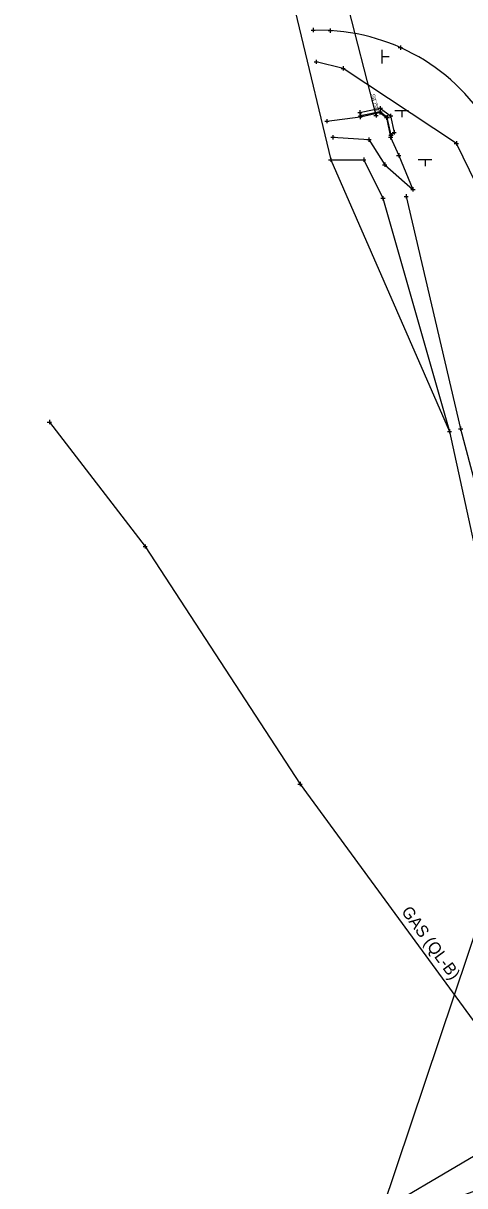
# Model space of a CAD drawing. Extents: x 2324380 to 2325559, y 691096 to 693386.
# Drawn here: x 2324982.9 to 2325086.8, y 691791.1 to 692064.7 of the extents above; entities that cross this region are included whole.
import ezdxf

# ---------------------------------------------------------------- set-up
doc = ezdxf.new("R2010")
doc.units = 0
for name, color, linetype in [('DR_X_Elev_Flow', 7, 'Continuous'), ('DR_X_Headwall', 7, 'Continuous'), ('DR_X_Storm_Sewer', 7, 'Continuous'), ('PV_X_EOP', 7, 'Continuous'), ('SC_Scratch1', 7, 'Continuous'), ('SN_X_Public', 7, 'Continuous'), ('SV_X_Shot_Marker', 7, 'Continuous'), ('SV_X_Terrain_Boundary', 7, 'Continuous'), ('SV_X_Toe_of_Slope', 7, 'Continuous'), ('SV_X_Top_of_Bank', 7, 'Continuous'), ('UT_X_Gas', 7, 'Continuous'), ('UT_X_Gas_Text', 7, 'Continuous')]:
    doc.layers.add(name, color=color, linetype=linetype)

msp = doc.modelspace()

# ---------------------------------------------------------------- linework, layer by layer
at = {"layer": 'DR_X_Elev_Flow'}
for p, q in [((2325065.42, 692043.03), (2325066.42, 692043.03)), ((2325065.92, 692043.53), (2325065.92, 692042.53)), ((2325065.92, 692043.03), (2325065.92, 692043.03))]:
    msp.add_line(p, q, dxfattribs=at)
at = {"layer": 'DR_X_Headwall'}
msp.add_lwpolyline([(2325062.28, 692042.98), (2325062.12, 692043.76), (2325066.93, 692044.75), (2325069.36, 692042.95), (2325070.2, 692039.04), (2325069.45, 692038.4), (2325068.56, 692042.58), (2325066.86, 692043.89)], close=True, dxfattribs=at)
at = {"layer": 'DR_X_Storm_Sewer'}
msp.add_line((2325065.92, 692043.03), (2325047.03, 692116.72), dxfattribs=at)
at = {"layer": 'PV_X_EOP'}
msp.add_line((2325055.16, 692062.99), (2325051.13, 692063.13), dxfattribs=at)
msp.add_arc((2325052.66, 692016.44), 46.62, 25.4715, 86.9224, dxfattribs=at)
at = {"layer": 'SN_X_Public'}
for p, q in [((2325067.39, 692055.3), (2325067.39, 692058.5)), ((2325067.39, 692056.9), (2325068.99, 692056.9)), ((2325070.36, 692044.2), (2325073.56, 692044.2)), ((2325071.96, 692044.2), (2325071.96, 692042.6)), ((2325075.86, 692032.68), (2325079.06, 692032.68)), ((2325077.46, 692032.68), (2325077.46, 692031.08))]:
    msp.add_line(p, q, dxfattribs=at)
at = {"layer": 'SV_X_Shot_Marker'}
for p, q in [((2325050.63, 692063.13), (2325051.63, 692063.13)), ((2325051.13, 692063.63), (2325051.13, 692062.63)), ((2325051.13, 692063.13), (2325051.13, 692063.13)), ((2325054.66, 692062.99), (2325055.66, 692062.99)), ((2325055.16, 692063.49), (2325055.16, 692062.49)), ((2325055.16, 692062.99), (2325055.16, 692062.99)), ((2325071.65, 692059.51), (2325071.65, 692058.51)), ((2325071.15, 692059.01), (2325072.15, 692059.01)), ((2325071.65, 692059.01), (2325071.65, 692059.01)), ((2325051.34, 692055.65), (2325052.34, 692055.65)), ((2325051.84, 692056.15), (2325051.84, 692055.15)), ((2325051.84, 692055.65), (2325051.84, 692055.65)), ((2325057.7, 692054.11), (2325058.7, 692054.11)), ((2325058.2, 692054.61), (2325058.2, 692053.61)), ((2325058.2, 692054.11), (2325058.2, 692054.11)), ((2325061.62, 692043.76), (2325062.62, 692043.76)), ((2325061.78, 692042.98), (2325062.78, 692042.98)), ((2325062.12, 692044.26), (2325062.12, 692043.26)), ((2325062.12, 692043.76), (2325062.12, 692043.76)), ((2325062.19, 692043.19), (2325062.19, 692042.19)), ((2325062.28, 692043.48), (2325062.28, 692042.48)), ((2325062.28, 692042.98), (2325062.28, 692042.98)), ((2325066.29, 692043.76), (2325067.29, 692043.76)), ((2325066.36, 692043.89), (2325067.36, 692043.89)), ((2325066.43, 692044.75), (2325067.43, 692044.75)), ((2325066.79, 692044.26), (2325066.79, 692043.26)), ((2325066.79, 692043.76), (2325066.79, 692043.76)), ((2325066.86, 692044.39), (2325066.86, 692043.39)), ((2325066.86, 692043.89), (2325066.86, 692043.89)), ((2325066.93, 692045.25), (2325066.93, 692044.25)), ((2325066.93, 692044.75), (2325066.93, 692044.75)), ((2325068.42, 692043.04), (2325068.42, 692042.04)), ((2325068.56, 692043.08), (2325068.56, 692042.08)), ((2325068.86, 692042.95), (2325069.86, 692042.95)), ((2325069.36, 692043.45), (2325069.36, 692042.45)), ((2325069.36, 692042.95), (2325069.36, 692042.95)), ((2325053.85, 692041.68), (2325054.85, 692041.68)), ((2325054.35, 692042.18), (2325054.35, 692041.18)), ((2325054.35, 692041.68), (2325054.35, 692041.68)), ((2325061.69, 692042.69), (2325062.69, 692042.69)), ((2325062.19, 692042.69), (2325062.19, 692042.69)), ((2325067.92, 692042.54), (2325068.92, 692042.54)), ((2325068.06, 692042.58), (2325069.06, 692042.58)), ((2325068.42, 692042.54), (2325068.42, 692042.54)), ((2325068.56, 692042.58), (2325068.56, 692042.58)), ((2325055.28, 692037.91), (2325056.28, 692037.91)), ((2325055.78, 692038.41), (2325055.78, 692037.41)), ((2325055.78, 692037.91), (2325055.78, 692037.91)), ((2325064.27, 692037.86), (2325064.27, 692036.86)), ((2325068.86, 692037.91), (2325069.86, 692037.91)), ((2325068.95, 692038.4), (2325069.95, 692038.4)), ((2325069.36, 692038.41), (2325069.36, 692037.41)), ((2325069.36, 692037.91), (2325069.36, 692037.91)), ((2325069.45, 692038.9), (2325069.45, 692037.9)), ((2325069.45, 692038.4), (2325069.45, 692038.4)), ((2325069.7, 692039.04), (2325070.7, 692039.04)), ((2325070.2, 692039.54), (2325070.2, 692038.54)), ((2325070.2, 692039.04), (2325070.2, 692039.04)), ((2325063.77, 692037.36), (2325064.77, 692037.36)), ((2325064.27, 692037.36), (2325064.27, 692037.36)), ((2325084.33, 692036.45), (2325085.33, 692036.45)), ((2325084.83, 692036.95), (2325084.83, 692035.95)), ((2325084.83, 692036.45), (2325084.83, 692036.45)), ((2325054.77, 692032.59), (2325055.77, 692032.59)), ((2325055.27, 692033.09), (2325055.27, 692032.09)), ((2325055.27, 692032.59), (2325055.27, 692032.59)), ((2325062.53, 692032.6), (2325063.53, 692032.6)), ((2325063.03, 692033.1), (2325063.03, 692032.1)), ((2325063.03, 692032.6), (2325063.03, 692032.6)), ((2325070.78, 692033.62), (2325071.78, 692033.62)), ((2325071.28, 692034.12), (2325071.28, 692033.12)), ((2325071.28, 692033.62), (2325071.28, 692033.62)), ((2325067.46, 692031.43), (2325068.46, 692031.43)), ((2325067.96, 692031.93), (2325067.96, 692030.93)), ((2325067.96, 692031.43), (2325067.96, 692031.43)), ((2325067.56, 692024.03), (2325067.56, 692023.03)), ((2325072.51, 692023.97), (2325073.51, 692023.97)), ((2325073.01, 692024.47), (2325073.01, 692023.47)), ((2325073.01, 692023.97), (2325073.01, 692023.97)), ((2325074.12, 692025.63), (2325075.12, 692025.63)), ((2325074.12, 692025.63), (2325075.12, 692025.63)), ((2325074.62, 692026.13), (2325074.62, 692025.13)), ((2325074.62, 692026.13), (2325074.62, 692025.13)), ((2325074.62, 692025.63), (2325074.62, 692025.63)), ((2325074.62, 692025.63), (2325074.62, 692025.63)), ((2325067.06, 692023.53), (2325068.06, 692023.53)), ((2325067.56, 692023.53), (2325067.56, 692023.53)), ((2324988.57, 691970.86), (2324989.57, 691970.86)), ((2324989.07, 691971.36), (2324989.07, 691970.36)), ((2324989.07, 691970.86), (2324989.07, 691970.86)), ((2325083.21, 691969.16), (2325083.21, 691968.16)), ((2325085.32, 691969.29), (2325086.32, 691969.29)), ((2325085.82, 691969.79), (2325085.82, 691968.79)), ((2325085.82, 691969.29), (2325085.82, 691969.29)), ((2325082.71, 691968.66), (2325083.71, 691968.66)), ((2325083.21, 691968.66), (2325083.21, 691968.66)), ((2325011.6, 691942.08), (2325011.6, 691941.08)), ((2325011.1, 691941.58), (2325012.1, 691941.58)), ((2325011.6, 691941.58), (2325011.6, 691941.58)), ((2325047.55, 691885.65), (2325048.55, 691885.65)), ((2325048.05, 691886.15), (2325048.05, 691885.15)), ((2325048.05, 691885.65), (2325048.05, 691885.65))]:
    msp.add_line(p, q, dxfattribs=at)
at = {"layer": 'SV_X_Terrain_Boundary'}
msp.add_lwpolyline([(2325040.39, 692094.78), (2325055.27, 692032.59), (2325083.21, 691968.66), (2325093.87, 691919.58), (2325094.39, 691865.88), (2325067.26, 691785.3), (2324974.04, 691758.93), (2324878.59, 691733.65), (2324786.86, 691712.89), (2324706.59, 691703.47), (2324706.71, 691700.83), (2324706.09, 691698.67)], dxfattribs=at)
at = {"layer": 'SV_X_Toe_of_Slope'}
for points in [[(2325054.35, 692041.68), (2325062.19, 692042.69), (2325066.79, 692043.76), (2325068.42, 692042.54), (2325069.36, 692037.91), (2325071.28, 692033.62), (2325074.62, 692025.63)], [(2325055.78, 692037.91), (2325064.27, 692037.36), (2325067.96, 692031.43), (2325074.62, 692025.63)], [(2325073.01, 692023.97), (2325085.82, 691969.29), (2325098.6, 691921.07), (2325104.84, 691866.44), (2325114.04, 691799.09), (2325069, 691782.4)]]:
    msp.add_lwpolyline(points, dxfattribs=at)
at = {"layer": 'SV_X_Top_of_Bank'}
for points in [[(2325089.45, 692026.9), (2325084.83, 692036.45), (2325058.2, 692054.11), (2325051.84, 692055.65)], [(2325055.27, 692032.59), (2325063.03, 692032.6), (2325067.56, 692023.53), (2325083.21, 691968.66), (2325093.87, 691919.58), (2325094.39, 691865.88), (2325105.07, 691807.57), (2325067.26, 691785.3)]]:
    msp.add_lwpolyline(points, dxfattribs=at)
at = {"layer": 'UT_X_Gas'}
msp.add_lwpolyline([(2324989.07, 691970.86), (2325011.6, 691941.58), (2325048.05, 691885.65), (2325093.46, 691823.6), (2325120.8, 691783.81), (2325138.43, 691746.33), (2325151.4, 691693.8), (2325156.77, 691659.76), (2325167.15, 691600.95), (2325171.48, 691564.26), (2325179.43, 691516.76), (2325185.5, 691470.97), (2325191.97, 691423.91), (2325198.27, 691377.48), (2325205.02, 691332.94), (2325213.79, 691283.13)], dxfattribs=at)

# ---------------------------------------------------------------- texts
at = {"layer": 'SC_Scratch1'}
msp.add_text("1162.85'", height=1, rotation=104.3729, dxfattribs=at).set_placement((2325066.89, 692043.28))
at = {"layer": 'UT_X_Gas_Text'}
msp.add_text('GAS (QL-B)', height=2.8, rotation=306.1958, dxfattribs=at).set_placement((2325071.76, 691855.62))

doc.saveas('drawing.dxf')
